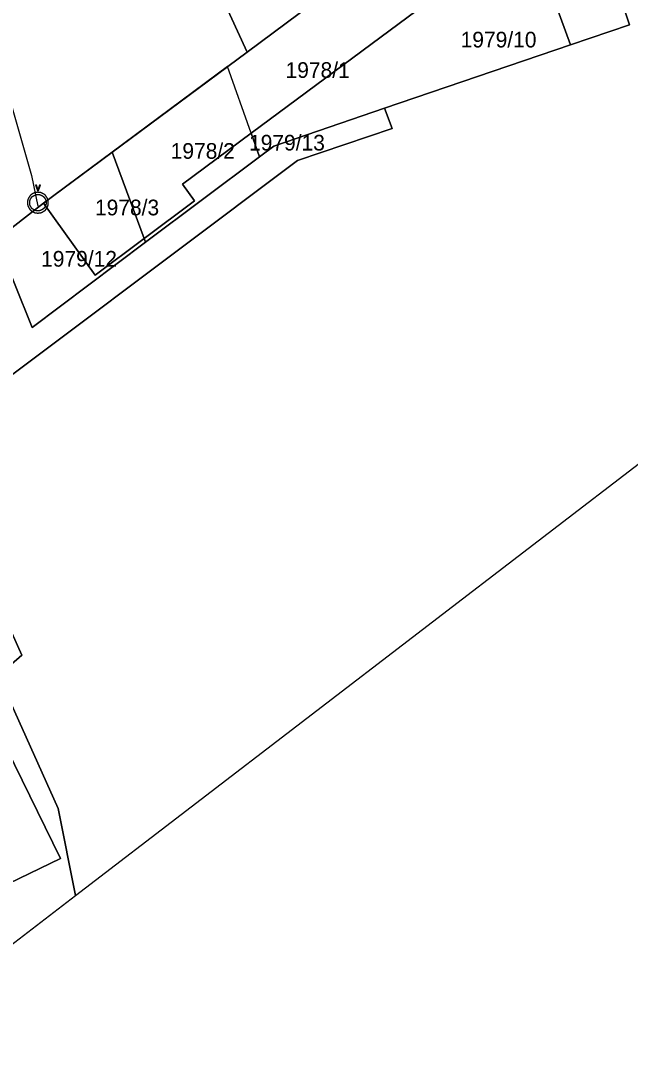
# Model space of a CAD drawing. Extents: x -570698 to -570232, y -1086952 to -1086596.
# Drawn here: x -570433 to -570374.7, y -1086923.8 to -1086825.7 of the extents above; entities that cross this region are included whole.
import ezdxf

# ---------------------------------------------------------------- set-up
doc = ezdxf.new("R2010")
doc.units = 0
for name, color, linetype in [('Default', 7, 'Continuous'), ('Parcela-polygon', 7, 'Continuous'), ('Parcela-text', 7, 'Continuous'), ('Vodovodní přípojka', 7, 'Continuous'), ('Vodovodní šachta', 7, 'Continuous')]:
    doc.layers.add(name, color=color, linetype=linetype)

msp = doc.modelspace()

# ---------------------------------------------------------------- linework, layer by layer
at = {"layer": 'Default'}
for points in [[(-570431.377, -1086841.862), (-570431.379, -1086841.844), (-570431.383, -1086841.833), (-570431.387, -1086841.828)], [(-570431.363, -1086841.828), (-570431.368, -1086841.837), (-570431.373, -1086841.849), (-570431.377, -1086841.862)], [(-570432.242, -1086842.631), (-570432.331, -1086842.791), (-570432.375, -1086842.957), (-570432.375, -1086843.13)], [(-570431.873, -1086842.266), (-570432.03, -1086842.35), (-570432.153, -1086842.472), (-570432.242, -1086842.631)], [(-570432.167, -1086843.13), (-570432.167, -1086842.994), (-570432.131, -1086842.863), (-570432.061, -1086842.737)], [(-570432.061, -1086842.737), (-570431.99, -1086842.612), (-570431.893, -1086842.516), (-570431.768, -1086842.449)], [(-570431.387, -1086842.139), (-570431.554, -1086842.139), (-570431.715, -1086842.181), (-570431.873, -1086842.266)], [(-570431.768, -1086842.449), (-570431.644, -1086842.381), (-570431.517, -1086842.348), (-570431.387, -1086842.348)], [(-570430.9, -1086842.266), (-570431.059, -1086842.181), (-570431.221, -1086842.139), (-570431.387, -1086842.139)], [(-570431.387, -1086842.348), (-570431.255, -1086842.348), (-570431.127, -1086842.381), (-570431.003, -1086842.449)], [(-570431.003, -1086842.449), (-570430.879, -1086842.516), (-570430.781, -1086842.612), (-570430.711, -1086842.737)], [(-570430.529, -1086842.631), (-570430.618, -1086842.472), (-570430.742, -1086842.35), (-570430.9, -1086842.266)], [(-570430.711, -1086842.737), (-570430.64, -1086842.863), (-570430.605, -1086842.994), (-570430.605, -1086843.13)], [(-570430.396, -1086843.13), (-570430.396, -1086842.957), (-570430.441, -1086842.791), (-570430.529, -1086842.631)], [(-570432.375, -1086843.13), (-570432.375, -1086843.301), (-570432.331, -1086843.465), (-570432.244, -1086843.621)], [(-570432.244, -1086843.621), (-570432.156, -1086843.777), (-570432.033, -1086843.899), (-570431.876, -1086843.987)], [(-570432.062, -1086843.517), (-570432.132, -1086843.394), (-570432.167, -1086843.265), (-570432.167, -1086843.13)], [(-570431.774, -1086843.804), (-570431.897, -1086843.735), (-570431.993, -1086843.64), (-570432.062, -1086843.517)], [(-570431.876, -1086843.987), (-570431.719, -1086844.074), (-570431.556, -1086844.118), (-570431.387, -1086844.118)], [(-570431.387, -1086843.906), (-570431.522, -1086843.906), (-570431.651, -1086843.872), (-570431.774, -1086843.804)], [(-570430.998, -1086843.804), (-570431.121, -1086843.872), (-570431.251, -1086843.906), (-570431.387, -1086843.906)], [(-570431.387, -1086844.118), (-570431.214, -1086844.118), (-570431.049, -1086844.074), (-570430.892, -1086843.987)], [(-570430.709, -1086843.517), (-570430.778, -1086843.64), (-570430.875, -1086843.735), (-570430.998, -1086843.804)], [(-570430.892, -1086843.987), (-570430.735, -1086843.899), (-570430.613, -1086843.777), (-570430.526, -1086843.621)], [(-570430.605, -1086843.13), (-570430.605, -1086843.265), (-570430.639, -1086843.394), (-570430.709, -1086843.517)], [(-570430.526, -1086843.621), (-570430.439, -1086843.465), (-570430.396, -1086843.301), (-570430.396, -1086843.13)]]:
    msp.add_open_spline(points, degree=2, dxfattribs=at)
at = {"layer": 'Parcela-polygon'}
for p, q in [((-570427.788, -1086909.426), (-570314.466, -1086822.423)), ((-570446.462, -1086923.763), (-570427.788, -1086909.426))]:
    msp.add_line(p, q, dxfattribs=at)
for points in [[(-570389.26, -1086812.25), (-570396.13, -1086801.76), (-570410.04, -1086810.86), (-570415.25, -1086802.82), (-570401.38, -1086793.74), (-570409.79, -1086780.91), (-570415.6, -1086784.7), (-570416.07, -1086784.05), (-570417.3, -1086784.9), (-570416.86, -1086785.52), (-570427.66, -1086792.57), (-570427.89, -1086792.8), (-570411.39, -1086828.72)], [(-570427.89, -1086792.8), (-570431.51, -1086799.19), (-570429.78, -1086801.48), (-570439.91, -1086809.64), (-570441.11, -1086808.13), (-570451.49, -1086816.45), (-570459.6, -1086820.01), (-570460.99, -1086822.22), (-570453.71, -1086837.46), (-570440.45, -1086850.62), (-570435.34, -1086846.66), (-570430.85, -1086843.19), (-570411.39, -1086828.72)], [(-570374.82, -1086826.12), (-570380.97, -1086807.48), (-570386.31, -1086810.04), (-570382.57, -1086815.36), (-570384.55, -1086816.83), (-570380.47, -1086828.04)], [(-570411.39, -1086828.72), (-570430.85, -1086843.19), (-570425.9, -1086850.06), (-570421.23, -1086846.55), (-570416.43, -1086842.95), (-570417.57, -1086841.37), (-570411, -1086836.49), (-570384.55, -1086816.83), (-570382.57, -1086815.36), (-570386.31, -1086810.04), (-570389.26, -1086812.25)], [(-570380.47, -1086828.04), (-570384.55, -1086816.83), (-570411, -1086836.49), (-570410.21, -1086838.75), (-570408.83, -1086837.72), (-570398.24, -1086834.1)], [(-570462.33, -1086820.69), (-570462.28, -1086820.13), (-570461.73, -1086819.28), (-570471.26, -1086826.6), (-570470.31, -1086826.04), (-570468.82, -1086825.8), (-570466.87, -1086826.17), (-570449.02, -1086853.9), (-570441.86, -1086860.44), (-570441.01, -1086861.21), (-570442.31, -1086864.93), (-570441.99, -1086865.7), (-570406.58, -1086839.09), (-570397.51, -1086836.02), (-570398.24, -1086834.1), (-570408.83, -1086837.72), (-570410.21, -1086838.75), (-570421.09, -1086846.92), (-570431.93, -1086855.06), (-570435.34, -1086846.66), (-570440.45, -1086850.62), (-570453.71, -1086837.46), (-570460.99, -1086822.22), (-570461.53, -1086822.52)], [(-570411, -1086836.49), (-570413.26, -1086830.1), (-570424.28, -1086838.3), (-570421.23, -1086846.55), (-570416.43, -1086842.95), (-570417.57, -1086841.37)], [(-570410.21, -1086838.75), (-570411, -1086836.49), (-570417.57, -1086841.37), (-570416.43, -1086842.95), (-570421.23, -1086846.55), (-570421.09, -1086846.92)], [(-570424.28, -1086838.3), (-570430.85, -1086843.19), (-570425.9, -1086850.06), (-570421.23, -1086846.55)], [(-570421.23, -1086846.55), (-570425.9, -1086850.06), (-570430.85, -1086843.19), (-570435.34, -1086846.66), (-570431.93, -1086855.06), (-570421.09, -1086846.92)], [(-570467.38, -1086889.2), (-570450.94, -1086916.37), (-570429.23, -1086905.88), (-570435.85, -1086892.39), (-570446.95, -1086897.96), (-570451.19, -1086889.31), (-570453.82, -1086897.33), (-570464.2, -1086886.11)]]:
    msp.add_lwpolyline(points, close=True, dxfattribs=at)
for points in [[(-570314.466, -1086822.423), (-570326.4, -1086786.46), (-570358.49, -1086797.03), (-570369.36, -1086800.59), (-570374.8, -1086803.82), (-570380.97, -1086807.48), (-570374.82, -1086826.12), (-570380.47, -1086828.04), (-570398.24, -1086834.1), (-570397.51, -1086836.02), (-570406.58, -1086839.09), (-570441.99, -1086865.7), (-570438.81, -1086873.31), (-570432.93, -1086886.42), (-570435.2, -1086888.38), (-570429.44, -1086901.1), (-570427.788, -1086909.426)], [(-570427.788, -1086909.426), (-570429.44, -1086901.1), (-570435.2, -1086888.38), (-570432.93, -1086886.42), (-570438.81, -1086873.31), (-570441.99, -1086865.7), (-570442.31, -1086864.93), (-570447.84, -1086880.26), (-570451.19, -1086889.31), (-570446.95, -1086897.96), (-570435.85, -1086892.39), (-570429.23, -1086905.88), (-570450.94, -1086916.37), (-570446.462, -1086923.763)]]:
    msp.add_lwpolyline(points, dxfattribs=at)
at = {"layer": 'Vodovodní přípojka'}
msp.add_lwpolyline([(-570444.41, -1086803.214), (-570444.311, -1086803.355), (-570443.997, -1086803.802), (-570442.263, -1086806.273), (-570442.168, -1086806.408), (-570440.515, -1086810.897), (-570438.558, -1086817.559), (-570436.308, -1086825.942), (-570433.913, -1086833.835), (-570432.002, -1086840.541), (-570431.385, -1086843.462)], dxfattribs=at)
at = {"layer": 'Vodovodní šachta'}
for points in [[(-570431.387, -1086841.828), (-570431.51, -1086841.469), (-570431.606, -1086841.469), (-570431.411, -1086841.972)], [(-570431.411, -1086841.972), (-570431.343, -1086841.972), (-570431.145, -1086841.469), (-570431.234, -1086841.469), (-570431.363, -1086841.828)]]:
    msp.add_lwpolyline(points, dxfattribs=at)

# ---------------------------------------------------------------- texts
at = {"layer": 'Parcela-text'}
for s, p in [('1979/10', (-570390.97, -1086828.28)), ('1978/1', (-570407.71, -1086831.19)), ('1979/13', (-570411.2, -1086838.14)), ('1978/2', (-570418.69, -1086838.93)), ('1978/3', (-570425.93, -1086844.34)), ('1979/12', (-570431.08, -1086849.25))]:
    msp.add_text(s, height=1.5, dxfattribs=at).set_placement(p)

doc.saveas('drawing.dxf')
